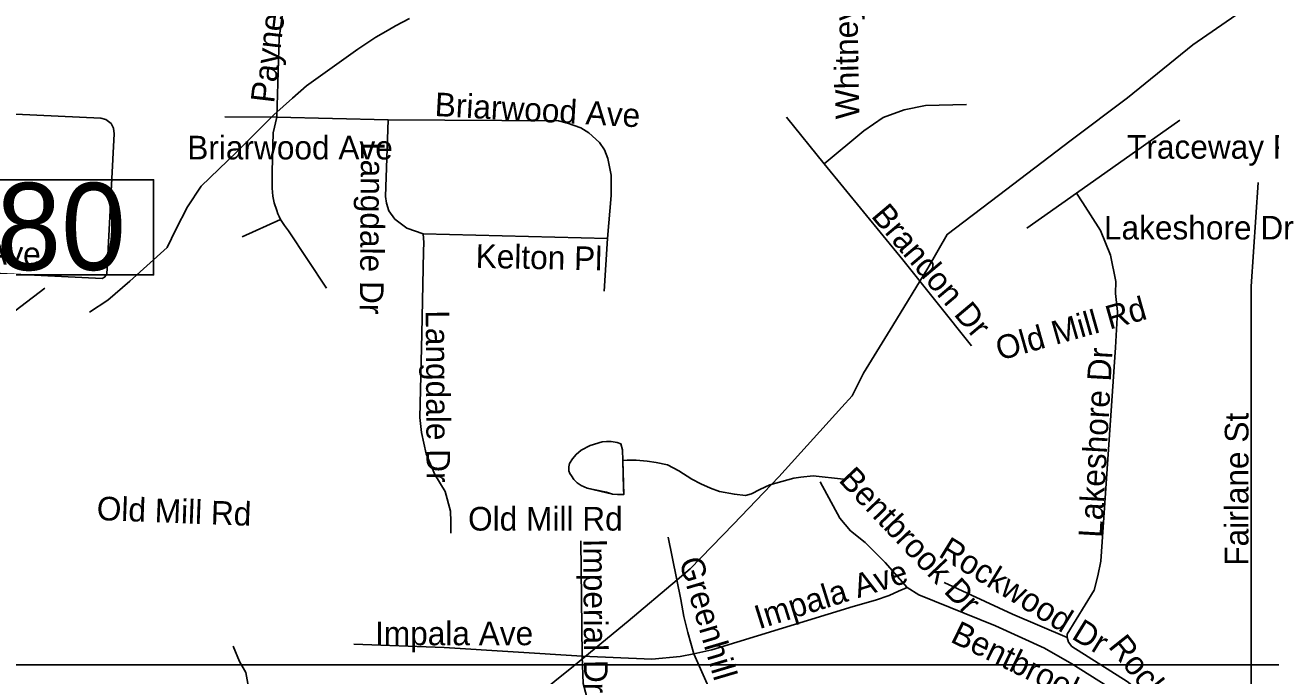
# Model space of a CAD drawing. Extents: x 1662474 to 1856135, y 779280 to 917889.
# Drawn here: x 1693341 to 1698345, y 826547 to 829158 of the extents above; entities that cross this region are included whole.
import ezdxf

# ---------------------------------------------------------------- set-up
doc = ezdxf.new("R2010")
doc.units = 0
for name, color, linetype in [('Exist Hydrographic Misc Water Feature', 7, 'Continuous'), ('Exist Road Non-System Type 51', 7, 'Continuous'), ('Exist Road Non-System Type 51 Label', 7, 'Continuous'), ('Exist Road Secondary Structure Standard Bridge Number Label', 7, 'Continuous'), ('Exist Utilities Electrical Transmission Line', 7, 'Continuous'), ('Map Preparation Inset Cut Line', 7, 'Continuous')]:
    doc.layers.add(name, color=color, linetype=linetype)

msp = doc.modelspace()

# ---------------------------------------------------------------- linework, layer by layer
at = {"layer": 'Exist Hydrographic Misc Water Feature'}
for points in [[(1693601.4, 828004.4), (1693674.2, 828052.1), (1693763.1, 828128.3), (1693912.9, 828264.7), (1693947.7, 828336.2), (1693995.1, 828428), (1694050.2, 828510.6), (1694191.8, 828647.3), (1694341.9, 828796.8), (1694416.8, 828864.2), (1694473.3, 828913.2), (1694679.3, 829060), (1694715.4, 829085.4), (1694751.7, 829108.5), (1694800.4, 829137.1), (1694830, 829153.7), (1694886.5, 829183.7)], [(1695743.4, 827408.5), (1695746.3, 827294.4), (1695747.8, 827272.2), (1695736.8, 827271.7), (1695722.1, 827272.8), (1695702.7, 827274), (1695678.1, 827281), (1695639.7, 827289.2), (1695601.1, 827297.3), (1695576.4, 827308.5), (1695560.4, 827318.7), (1695546.6, 827333), (1695537, 827347.1), (1695531, 827357.1), (1695527.2, 827367), (1695527, 827383.4), (1695529.6, 827397.3), (1695541.4, 827415.1), (1695555.9, 827432.9), (1695576.3, 827450.6), (1695612.3, 827469.5), (1695660.7, 827483.3), (1695678.7, 827485.4), (1695696.9, 827485), (1695720.6, 827480.4), (1695736.5, 827476), (1695742.3, 827452.1), (1695743.4, 827408.5)], [(1695743.4, 827408.5), (1695747.8, 827272.2), (1695736.8, 827271.7), (1695702.7, 827274), (1695601.1, 827297.3), (1695576.4, 827308.5), (1695560.4, 827318.7), (1695546.6, 827333), (1695537, 827347.1), (1695531, 827357.1), (1695527.2, 827367), (1695527, 827383.4), (1695529.6, 827397.3), (1695541.4, 827415.1), (1695555.9, 827432.9), (1695576.3, 827450.6), (1695612.3, 827469.5), (1695660.7, 827483.3), (1695678.7, 827485.4), (1695696.9, 827485), (1695720.6, 827480.4), (1695736.5, 827476), (1695742.3, 827452.1), (1695743.4, 827408.5)], [(1695743.4, 827408.5), (1695761.4, 827410.7), (1695797.4, 827410.7), (1695841.3, 827406.5), (1695877.2, 827400.1), (1695923.2, 827391.8), (1695969.1, 827367.1), (1696020.9, 827333.2), (1696056.7, 827314.4), (1696096.4, 827298), (1696132.6, 827284.1), (1696192.5, 827273), (1696236.5, 827268.8), (1696260.6, 827274.9), (1696294.6, 827292.3), (1696334.7, 827310.4), (1696431.1, 827337.9), (1696459.6, 827342.3), (1696509.2, 827347.1), (1696630.1, 827333.9)], [(1694177.9, 826662.5), (1694203.2, 826602), (1694228.6, 826558), (1694247.2, 826461.7)]]:
    msp.add_lwpolyline(points, dxfattribs=at)
at = {"layer": 'Exist Road Non-System Type 51'}
for p, q in [((1694354.1, 828788.1), (1694144.6, 828789.2)), ((1694801.1, 828776.6), (1694354.1, 828788.1)), ((1696552.8, 828599.7), (1696400.9, 828787.1)), ((1697566.1, 828482.6), (1697981.4, 828776)), ((1697366.9, 828341.7), (1697566.1, 828482.6)), ((1698268.2, 828107.9), (1698297.1, 828525.7)), ((1694215, 828306.5), (1694367.8, 828377.1)), ((1694941.9, 828318.4), (1695681.9, 828300.8)), ((1695669.4, 828088.9), (1695681.9, 828300.8)), ((1695580.1, 826623.4), (1695575.6, 827085.5)), ((1694663.6, 826670.6), (1695026.1, 826657.4)), ((1695026.1, 826657.4), (1695580.1, 826623.4))]:
    msp.add_line(p, q, dxfattribs=at)
for points in [[(1694354.1, 828788.1), (1694363.6, 829105.9), (1694376.1, 829201.8), (1694396.9, 829297.2)], [(1691842.6, 828231.7), (1691934.5, 828224.1), (1693652.1, 828139.9), (1693661.8, 828144.9), (1693670.6, 828157.4), (1693699.9, 828720.2), (1693697.8, 828743), (1693687.5, 828762.1), (1693667.2, 828778.2), (1693646.6, 828784.2), (1691901.4, 828865.2)], [(1696552.8, 828599.7), (1696712.4, 828733.2), (1696790.4, 828785.8), (1696874.9, 828817.5), (1696960.4, 828834), (1697124.6, 828838)], [(1694367.8, 828377.1), (1694362.6, 828388.7), (1694357.9, 828398.9), (1694353.6, 828412.5), (1694342.9, 828443.2), (1694337.9, 828470.5), (1694335, 828501.8), (1694334.8, 828533.5), (1694335.5, 828572.4), (1694336.4, 828615.9), (1694337.1, 828675.5), (1694338.6, 828724.4), (1694354.1, 828788.1)], [(1694941.9, 828318.4), (1694876.1, 828341.2), (1694828.1, 828377.6), (1694804, 828410.9), (1694794.9, 828442.2), (1694790.6, 828469.5), (1694801.1, 828776.6)], [(1695681.9, 828300.8), (1695697.6, 828472.4), (1695697.6, 828554.8), (1695683, 828621.4), (1695669.6, 828655.9), (1695649.6, 828686), (1695607.1, 828724.6), (1695574.9, 828744.2), (1695522.1, 828763.7), (1695484.9, 828773.2), (1694801.1, 828776.6)], [(1697145.4, 827868.7), (1696868.5, 828214.1), (1696552.8, 828599.7)], [(1697723.6, 828079.2), (1697724.6, 828127.8), (1697702.9, 828233), (1697663.2, 828331.9), (1697591.9, 828443.5), (1697566.1, 828482.6)], [(1694552.9, 828100.8), (1694400.9, 828331.4), (1694384.6, 828352.9), (1694367.8, 828377.1)], [(1695053.1, 827117.2), (1695053.1, 827163.2), (1695051, 827204.7), (1695030.2, 827283.9), (1694988.8, 827351.9), (1694953.6, 827434.9), (1694934.4, 827521.5), (1694928.9, 827581.4), (1694935.8, 827917.2), (1694942.4, 828248), (1694943.9, 828283.9), (1694941.9, 828318.4)], [(1697529.9, 826698.1), (1697529.9, 826710.8), (1697637.2, 826888.4), (1697653, 826945.9), (1697664.4, 827003.9), (1697723.6, 827862.2), (1697731.8, 828007.6), (1697723.6, 828079.2)], [(1698082.1, 826196.6), (1698219.4, 826279.5), (1698253.9, 826314.9), (1698268.5, 826347.5), (1698268.2, 828107.9)], [(1696886.1, 826899.2), (1696797.4, 826998.7), (1696717.9, 827079.5), (1696658.6, 827126.8), (1696616.4, 827176.9), (1696536.2, 827323.6)], [(1696028.9, 826633), (1696005, 826718.6), (1695989.6, 826782.1), (1695976.9, 826849.9), (1695925.8, 827101.5)], [(1696028.9, 826633), (1696101.9, 826647.8), (1696669.6, 826821.8), (1696759.1, 826847.8), (1696813.4, 826866.6), (1696851.8, 826884.2), (1696886.1, 826899.2)], [(1697981.6, 826131.2), (1697857, 826340.4), (1697811.4, 826401.9), (1697764.6, 826452.8), (1697728.6, 826478.4), (1697547.8, 826591.6), (1697438.1, 826655.1), (1697241.5, 826745.4), (1696933.1, 826869.2), (1696886.1, 826899.2)], [(1697529.9, 826698.1), (1697309.8, 826791.4), (1697035.4, 826918.4)], [(1698082.1, 826196.6), (1697927.6, 826341.7), (1697884.5, 826406.8), (1697846.1, 826452.8), (1697807.6, 826491.4), (1697770.1, 826521.5), (1697548.6, 826662.2), (1697534.9, 826679), (1697529.9, 826698.1)], [(1695580.1, 826623.4), (1695860.1, 826611.2), (1695973.9, 826621.8), (1696028.9, 826633)], [(1696334.4, 826101), (1696098.8, 826475.9), (1696028.9, 826633)], [(1696278, 825297.9), (1695638.4, 826357.2), (1695602.9, 826443.5), (1695585.1, 826513.1), (1695580.1, 826623.4)]]:
    msp.add_lwpolyline(points, dxfattribs=at)
at = {"layer": 'Exist Road Secondary Structure Standard Bridge Number Label'}
msp.add_line((1691740.1, 826815.3), (1693421.9, 828101.4), dxfattribs=at)
msp.add_lwpolyline([(1693214.3, 828536.2), (1693858.4, 828536.2), (1693858.4, 828153.9), (1693214.3, 828153.9)], close=True, dxfattribs=at)
at = {"layer": 'Exist Utilities Electrical Transmission Line'}
msp.add_lwpolyline([(1695327.8, 826406.8), (1695545.6, 826582.5), (1695765.9, 826764.1), (1695961.7, 826930), (1696014.2, 826973.4), (1696188.2, 827153.6), (1696370.4, 827343.6), (1696623.6, 827623), (1696665.9, 827668.6), (1696711, 827760.1), (1696829.1, 827950.8), (1696969.7, 828181.5), (1697047.3, 828316.6), (1697253, 828472.5), (1697545.6, 828695.3), (1697771.4, 828864.8), (1698033.9, 829078), (1698284, 829251.4)], dxfattribs=at)
at = {"layer": 'Map Preparation Inset Cut Line'}
for points in [[(1731035.7, 826588.1), (1668486.3, 826588.1), (1668486.3, 870408.9), (1731035.7, 870408.9)], [(1731035.7, 782767.4), (1668486.3, 782767.4), (1668486.3, 826588.1), (1731035.7, 826588.1)]]:
    msp.add_lwpolyline(points, close=True, dxfattribs=at)

# ---------------------------------------------------------------- texts
at = {"layer": 'Exist Road Non-System Type 51 Label'}
for s, rotation, p in [('Payne Rd', 83.1902, (1694342.5, 828841.2)), ('Whitney Ct', 90.9723, (1696694.2, 828780.3)), ('Briarwood Ave', 356.8159, (1694986.3, 828792.5)), ('Langdale Dr', 269.5496, (1694692.3, 828688.1)), ('Brandon Dr', 310.1425, (1696738.3, 828389.2)), ('Bridlewood Ave', 357.5844, (1692521.2, 828226.6)), ('Kelton Pl', 358.7664, (1695151.8, 828182.8)), ('Old Mill Rd', 15.7764, (1697258, 827809.4)), ('Langdale Dr', 270.2662, (1694952.1, 828012)), ('Lakeshore Dr', 86.797, (1697669.2, 827097)), ('Fairlane St', 90, (1698257.7, 826986.2)), ('Bentbrook Dr', 313.4557, (1696607.5, 827327.4)), ('Old Mill Rd', 357.8266, (1693628.8, 827169.8)), ('Imperial Dr', 270.353, (1695584.9, 827094.8)), ('Rockwood Dr', 328.3342, (1697007.7, 827025.8)), ('Greenhill Dr', 286.4604, (1695969, 827005.7)), ('Impala Ave', 17.4638, (1696291.1, 826730.6)), ('Bentbrook Dr', 333.8931, (1697055.6, 826682.4)), ('Rockwood Dr', 308.5345, (1697691.4, 826661.2))]:
    msp.add_text(s, height=95, rotation=rotation, dxfattribs=at).set_placement(p)
for s, p in [('Briarwood Ave', (1693993.8, 828617.9)), ('Traceway Rd', (1697769.8, 828620.7)), ('Lakeshore Dr', (1697676.9, 828296.3)), ('Old Mill Rd', (1695122.1, 827127.4)), ('Impala Ave', (1694748.3, 826666.9))]:
    msp.add_text(s, height=95, dxfattribs=at).set_placement(p)
at = {"layer": 'Exist Road Secondary Structure Standard Bridge Number Label'}
msp.add_text('80', height=350, dxfattribs=at).set_placement((1693226.9, 828173.7))

doc.saveas('drawing.dxf')
